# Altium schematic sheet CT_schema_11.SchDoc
size 281 x 153 mm
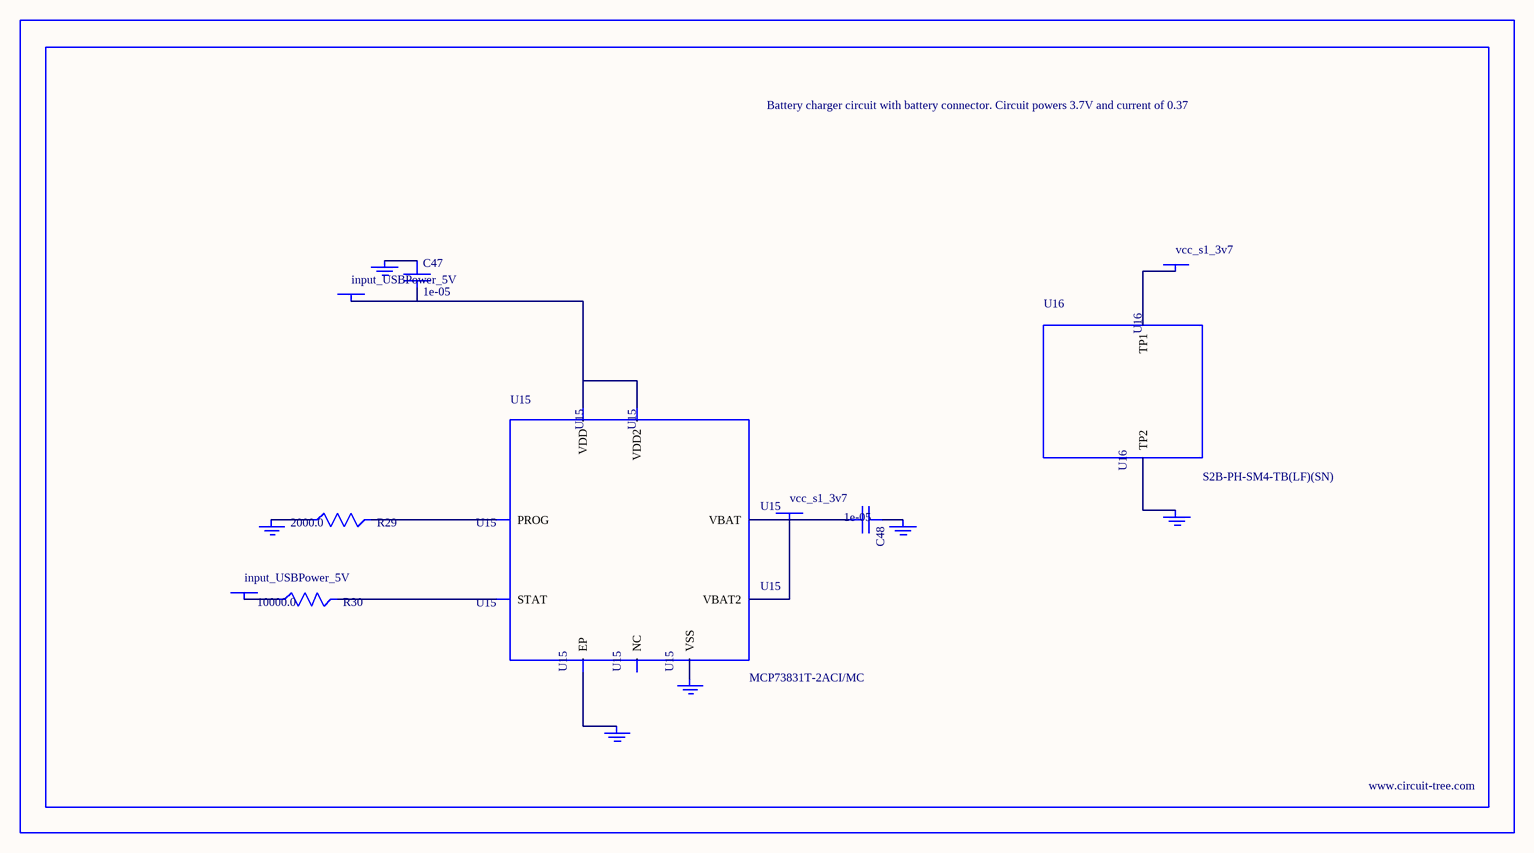
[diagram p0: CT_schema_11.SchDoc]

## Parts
BORDER10  (no value)
C47  1e-05  [C1206]
C48  1e-05  [C1206]
GND_INSTANCE_10_0  (no value)
GND_INSTANCE_10_1  (no value)
GND_INSTANCE_10_2  (no value)
GND_INSTANCE_10_3  (no value)
GND_INSTANCE_10_4  (no value)
GND_INSTANCE_10_5  (no value)
POWER_INSTANCE_10_0  input_USBPower_5V
POWER_INSTANCE_10_1  input_USBPower_5V
POWER_INSTANCE_10_2  vcc_s1_3v7
POWER_INSTANCE_10_3  vcc_s1_3v7
R29  2000.0  [R0603]
R30  10000.0  [R0603]
U15  MCP73831T-2ACI/MC  [DFN8_2X3MC]
U16  S2B-PH-SM4-TB(LF)(SN)  [JST-2-SMD]

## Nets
NetC47_1: C47.1 GND_INSTANCE_10_0.0(GND)
NetC47_2: C47.2 POWER_INSTANCE_10_0.0(PWR) U15.1(VDD) U15.2(VDD2)
NetC48_1: C48.1 GND_INSTANCE_10_1.0(GND)
NetC48_2: C48.2 POWER_INSTANCE_10_2.0(PWR) U15.3(VBAT) U15.4(VBAT2)
NetGND_INSTANCE_10_2_0: GND_INSTANCE_10_2.0(GND) R29.1
NetGND_INSTANCE_10_3_0: GND_INSTANCE_10_3.0(GND) U15.9(EP)
NetGND_INSTANCE_10_4_0: GND_INSTANCE_10_4.0(GND) U15.6(VSS)
NetGND_INSTANCE_10_5_0: GND_INSTANCE_10_5.0(GND) U16.2(TP2)
NetPOWER_INSTANCE_10_1_0: POWER_INSTANCE_10_1.0(PWR) R30.1
NetPOWER_INSTANCE_10_3_0: POWER_INSTANCE_10_3.0(PWR) U16.1(TP1)
NetR29_2: R29.2 U15.8(PROG)
NetR30_2: R30.2 U15.5(STAT)

Not connected (* = marked no-connect by the designer): U15 7(NC)

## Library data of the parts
BORDER10 = BORDER_PAGE10
C47 C48 = C1206C106K3RACTU
GND_INSTANCE_10_0-GND_INSTANCE_10_5 = GND
POWER_INSTANCE_10_0-POWER_INSTANCE_10_3 = PWR
R29 = RC0603JR-072KL
R30 = RC0603JR-0710KL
